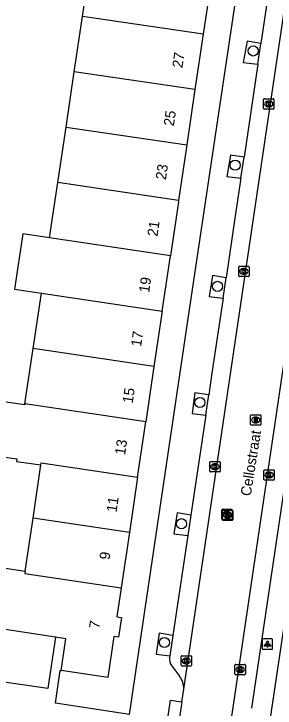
# Model space of a CAD drawing. Extents: x 164150 to 165261, y 382513 to 383432.
# Drawn here: x 164314.2 to 164339.4, y 382927.8 to 382994.8 of the extents above; entities that cross this region are included whole.
import ezdxf

# ---------------------------------------------------------------- set-up
doc = ezdxf.new("R2010")
doc.units = 0
for name, color, linetype in [('IMGEO_Boom', 7, 'Continuous'), ('IMGEO_Kolk', 7, 'Continuous'), ('IMGEO_Lichtpunt', 7, 'Continuous'), ('IMGEO_Openbare_ruimte_label', 7, 'Continuous'), ('IMGEO_Pand', 7, 'Continuous'), ('IMGEO_Pand_nummerreeks', 7, 'Continuous'), ('IMGEO_Parkeervlak_open', 7, 'Continuous'), ('IMGEO_Rijbaan_lokaal_open', 7, 'Continuous'), ('IMGEO_Rioolput', 7, 'Continuous'), ('IMGEO_Voetpad_open', 7, 'Continuous')]:
    doc.layers.add(name, color=color, linetype=linetype)

msp = doc.modelspace()

# ---------------------------------------------------------------- linework, layer by layer
at = {"layer": 'IMGEO_Boom'}
for centre in [(164337.291, 382991.232), (164335.553, 382980.21), (164333.847, 382968.518), (164332.146, 382957.302), (164330.362, 382945.609), (164328.715, 382934.147)]:
    msp.add_circle(centre, 0.489, dxfattribs=at)
at = {"layer": 'IMGEO_Kolk'}
for p, q in [((164338.283, 382985.695), (164338.283, 382986.547)), ((164338.358, 382986.621), (164339.21, 382986.621)), ((164338.771, 382986.401), (164338.796, 382986.401)), ((164339.284, 382986.547), (164339.284, 382985.695)), ((164339.21, 382985.621), (164338.358, 382985.621)), ((164338.794, 382985.841), (164338.769, 382985.841)), ((164335.89, 382969.532), (164335.89, 382970.384)), ((164335.965, 382970.458), (164336.817, 382970.458)), ((164336.378, 382970.238), (164336.403, 382970.238)), ((164336.891, 382970.384), (164336.891, 382969.532)), ((164336.401, 382969.678), (164336.376, 382969.678)), ((164336.817, 382969.458), (164335.965, 382969.458)), ((164333.098, 382950.684), (164333.098, 382951.536)), ((164333.173, 382951.61), (164334.025, 382951.61)), ((164334.099, 382951.536), (164334.099, 382950.684)), ((164333.609, 382950.83), (164333.584, 382950.83)), ((164333.586, 382951.39), (164333.611, 382951.39)), ((164338.312, 382949.883), (164338.312, 382950.735)), ((164338.387, 382950.809), (164339.239, 382950.809)), ((164339.313, 382950.735), (164339.313, 382949.883)), ((164334.025, 382950.61), (164333.173, 382950.61)), ((164338.8, 382950.589), (164338.825, 382950.589)), ((164339.239, 382949.809), (164338.387, 382949.809)), ((164338.823, 382950.029), (164338.798, 382950.029)), ((164330.332, 382931.941), (164330.332, 382932.793)), ((164330.407, 382932.867), (164331.259, 382932.867)), ((164330.82, 382932.647), (164330.845, 382932.647)), ((164331.333, 382932.793), (164331.333, 382931.941)), ((164330.843, 382932.087), (164330.818, 382932.087)), ((164335.6, 382932.034), (164336.452, 382932.034)), ((164331.259, 382931.867), (164330.407, 382931.867)), ((164335.525, 382931.108), (164335.525, 382931.96)), ((164336.013, 382931.814), (164336.038, 382931.814)), ((164336.526, 382931.96), (164336.526, 382931.108)), ((164336.452, 382931.034), (164335.6, 382931.034)), ((164336.036, 382931.254), (164336.011, 382931.254))]:
    msp.add_line(p, q, dxfattribs=at)
for points in [[(164338.283, 382985.695), (164338.283, 382986.547)], [(164338.358, 382986.621), (164339.21, 382986.621)], [(164338.604, 382986.321), (164338.727, 382986.321), (164338.727, 382986.17), (164338.857, 382986.321), (164339.021, 382986.321), (164338.875, 382986.17), (164339.028, 382985.921), (164338.876, 382985.921), (164338.791, 382986.085), (164338.727, 382986.018), (164338.727, 382985.921), (164338.604, 382985.921), (164338.604, 382986.321)], [(164339.284, 382986.547), (164339.284, 382985.695)], [(164339.21, 382985.621), (164338.358, 382985.621)], [(164335.89, 382969.532), (164335.89, 382970.384)], [(164335.965, 382970.458), (164336.817, 382970.458)], [(164336.891, 382970.384), (164336.891, 382969.532)], [(164336.211, 382970.158), (164336.334, 382970.158), (164336.334, 382970.007), (164336.464, 382970.158), (164336.628, 382970.158), (164336.482, 382970.007), (164336.635, 382969.758), (164336.483, 382969.758), (164336.398, 382969.922), (164336.334, 382969.855), (164336.334, 382969.758), (164336.211, 382969.758), (164336.211, 382970.158)], [(164336.817, 382969.458), (164335.965, 382969.458)], [(164333.098, 382950.684), (164333.098, 382951.536)], [(164333.173, 382951.61), (164334.025, 382951.61)], [(164334.099, 382951.536), (164334.099, 382950.684)], [(164333.419, 382951.31), (164333.542, 382951.31), (164333.542, 382951.159), (164333.672, 382951.31), (164333.836, 382951.31), (164333.69, 382951.159), (164333.843, 382950.91), (164333.691, 382950.91), (164333.606, 382951.074), (164333.542, 382951.007), (164333.542, 382950.91), (164333.419, 382950.91), (164333.419, 382951.31)], [(164338.312, 382949.883), (164338.312, 382950.735)], [(164338.387, 382950.809), (164339.239, 382950.809)], [(164339.313, 382950.735), (164339.313, 382949.883)], [(164334.025, 382950.61), (164333.173, 382950.61)], [(164338.633, 382950.509), (164338.756, 382950.509), (164338.756, 382950.358), (164338.886, 382950.509), (164339.05, 382950.509), (164338.904, 382950.358), (164339.057, 382950.109), (164338.905, 382950.109), (164338.82, 382950.273), (164338.756, 382950.206), (164338.756, 382950.109), (164338.633, 382950.109), (164338.633, 382950.509)], [(164339.239, 382949.809), (164338.387, 382949.809)], [(164330.332, 382931.941), (164330.332, 382932.793)], [(164330.407, 382932.867), (164331.259, 382932.867)], [(164331.333, 382932.793), (164331.333, 382931.941)], [(164330.653, 382932.567), (164330.776, 382932.567), (164330.776, 382932.416), (164330.906, 382932.567), (164331.07, 382932.567), (164330.924, 382932.416), (164331.077, 382932.167), (164330.925, 382932.167), (164330.84, 382932.331), (164330.776, 382932.264), (164330.776, 382932.167), (164330.653, 382932.167), (164330.653, 382932.567)], [(164335.6, 382932.034), (164336.452, 382932.034)], [(164331.259, 382931.867), (164330.407, 382931.867)], [(164335.525, 382931.108), (164335.525, 382931.96)], [(164335.846, 382931.734), (164335.969, 382931.734), (164335.969, 382931.583), (164336.099, 382931.734), (164336.263, 382931.734), (164336.117, 382931.583), (164336.27, 382931.334), (164336.118, 382931.334), (164336.033, 382931.498), (164335.969, 382931.431), (164335.969, 382931.334), (164335.846, 382931.334), (164335.846, 382931.734)], [(164336.526, 382931.96), (164336.526, 382931.108)], [(164336.452, 382931.034), (164335.6, 382931.034)]]:
    msp.add_lwpolyline(points, dxfattribs=at)
for centre, start, end in [((164338.36, 382986.545), 91.55205, 178.44795), ((164338.36, 382986.545), 91.55205, 178.44795), ((164339.208, 382986.545), 1.55205, 88.44795), ((164339.208, 382986.545), 1.55205, 88.44795), ((164338.36, 382985.697), 181.55205, 268.44795), ((164338.36, 382985.697), 181.55205, 268.44795), ((164339.208, 382985.697), 271.55205, 358.44795), ((164339.208, 382985.697), 271.55205, 358.44795), ((164335.967, 382970.382), 91.55205, 178.44795), ((164335.967, 382970.382), 91.55205, 178.44795), ((164336.815, 382970.382), 1.55205, 88.44795), ((164336.815, 382970.382), 1.55205, 88.44795), ((164335.967, 382969.534), 181.55205, 268.44795), ((164335.967, 382969.534), 181.55205, 268.44795), ((164336.815, 382969.534), 271.55205, 358.44795), ((164336.815, 382969.534), 271.55205, 358.44795), ((164333.175, 382951.534), 91.55205, 178.44795), ((164333.175, 382951.534), 91.55205, 178.44795), ((164334.023, 382951.534), 1.55205, 88.44795), ((164334.023, 382951.534), 1.55205, 88.44795), ((164338.389, 382950.733), 91.55205, 178.44795), ((164338.389, 382950.733), 91.55205, 178.44795), ((164339.237, 382950.733), 1.55205, 88.44795), ((164339.237, 382950.733), 1.55205, 88.44795), ((164333.175, 382950.686), 181.55205, 268.44795), ((164333.175, 382950.686), 181.55205, 268.44795), ((164334.023, 382950.686), 271.55205, 358.44795), ((164334.023, 382950.686), 271.55205, 358.44795), ((164338.389, 382949.885), 181.55205, 268.44795), ((164338.389, 382949.885), 181.55205, 268.44795), ((164339.237, 382949.885), 271.55205, 358.44795), ((164339.237, 382949.885), 271.55205, 358.44795), ((164330.409, 382932.791), 91.55205, 178.44795), ((164330.409, 382932.791), 91.55205, 178.44795), ((164331.257, 382932.791), 1.55205, 88.44795), ((164331.257, 382932.791), 1.55205, 88.44795), ((164335.602, 382931.958), 91.55205, 178.44795), ((164335.602, 382931.958), 91.55205, 178.44795), ((164336.45, 382931.958), 1.55205, 88.44795), ((164336.45, 382931.958), 1.55205, 88.44795), ((164330.409, 382931.943), 181.55205, 268.44795), ((164330.409, 382931.943), 181.55205, 268.44795), ((164331.257, 382931.943), 271.55205, 358.44795), ((164331.257, 382931.943), 271.55205, 358.44795), ((164335.602, 382931.11), 181.55205, 268.44795), ((164335.602, 382931.11), 181.55205, 268.44795), ((164336.45, 382931.11), 271.55205, 358.44795), ((164336.45, 382931.11), 271.55205, 358.44795)]:
    msp.add_arc(centre, 0.0765, start, end, dxfattribs=at)
for centre, major_axis, ratio, start_param, end_param in [((164338.77, 382986.121), (-0.387, 0.002), 0.722429, 4.712389, 7.853982), ((164338.795, 382986.121), (-0.39, 0.002), 0.717154, 1.570796, 4.712389), ((164336.377, 382969.958), (-0.387, 0.002), 0.722429, 4.712389, 7.853982), ((164336.402, 382969.958), (-0.39, 0.002), 0.717154, 1.570796, 4.712389), ((164333.585, 382951.11), (-0.387, 0.002), 0.722429, 4.712389, 7.853982), ((164333.61, 382951.11), (-0.39, 0.002), 0.717154, 1.570796, 4.712389), ((164338.799, 382950.309), (-0.387, 0.002), 0.722429, 4.712389, 7.853982), ((164338.824, 382950.309), (-0.39, 0.002), 0.717154, 1.570796, 4.712389), ((164330.819, 382932.367), (-0.387, 0.002), 0.722429, 4.712389, 7.853982), ((164330.844, 382932.367), (-0.39, 0.002), 0.717154, 1.570796, 4.712389), ((164336.012, 382931.534), (-0.387, 0.002), 0.722429, 4.712389, 7.853982), ((164336.037, 382931.534), (-0.39, 0.002), 0.717154, 1.570796, 4.712389)]:
    msp.add_ellipse(centre, major_axis=major_axis, ratio=ratio, start_param=start_param, end_param=end_param, dxfattribs=at)
at = {"layer": 'IMGEO_Lichtpunt'}
for p, q in [((164338.163, 382934.391), (164338.163, 382933.584)), ((164338.163, 382934.391), (164338.163, 382933.584)), ((164339.065, 382934.486), (164338.257, 382934.486)), ((164339.065, 382934.486), (164338.257, 382934.486)), ((164339.159, 382933.584), (164339.159, 382934.391)), ((164339.159, 382933.584), (164339.159, 382934.391)), ((164338.257, 382933.49), (164339.065, 382933.49)), ((164338.257, 382933.49), (164339.065, 382933.49))]:
    msp.add_line(p, q, dxfattribs=at)
for points in [[(164338.537, 382934.055), (164338.576, 382934.027), (164338.388, 382933.765), (164338.35, 382933.792), (164338.537, 382934.055)], [(164338.639, 382934.007), (164338.686, 382934.007), (164338.686, 382933.685), (164338.639, 382933.685), (164338.639, 382934.007)], [(164338.749, 382934.027), (164338.787, 382934.054), (164338.974, 382933.792), (164338.935, 382933.764), (164338.749, 382934.027)]]:
    msp.add_lwpolyline(points, dxfattribs=at)
msp.add_circle((164338.662, 382934.189), 0.0994, dxfattribs=at)
for centre, start, end in [((164338.257, 382934.391), 90, 180), ((164338.257, 382934.391), 90, 180), ((164339.065, 382934.391), 0, 90), ((164339.065, 382934.391), 0, 90), ((164338.257, 382933.584), 180, 270), ((164338.257, 382933.584), 180, 270), ((164339.065, 382933.584), 270, 0), ((164339.065, 382933.584), 270, 360)]:
    msp.add_arc(centre, 0.0946, start, end, dxfattribs=at)
at = {"layer": 'IMGEO_Pand'}
for points in [[(164320.82, 382994.569), (164321.613, 382999.909)], [(164333.248, 382998.185), (164332.457, 382992.844)], [(164320.027, 382989.227), (164320.82, 382994.569)], [(164332.457, 382992.844), (164320.82, 382994.569)], [(164332.457, 382992.844), (164331.667, 382987.502)], [(164319.233, 382983.885), (164320.027, 382989.227)], [(164331.667, 382987.502), (164320.027, 382989.227)], [(164331.667, 382987.502), (164330.877, 382982.159)], [(164318.44, 382978.544), (164319.233, 382983.885)], [(164319.233, 382983.885), (164330.877, 382982.159)], [(164330.877, 382982.159), (164330.086, 382976.818)], [(164317.647, 382973.203), (164318.44, 382978.544)], [(164330.086, 382976.818), (164318.44, 382978.544)], [(164330.086, 382976.818), (164330.067, 382976.687), (164329.295, 382971.476)], [(164317.647, 382973.203), (164315.055, 382973.587), (164314.262, 382968.245), (164316.854, 382967.861)], [(164329.295, 382971.476), (164317.647, 382973.203)], [(164328.504, 382966.134), (164329.295, 382971.476)], [(164316.061, 382962.52), (164316.854, 382967.861)], [(164316.854, 382967.861), (164328.504, 382966.134)], [(164328.504, 382966.134), (164327.713, 382960.793)], [(164315.267, 382957.178), (164316.061, 382962.52)], [(164327.713, 382960.793), (164316.061, 382962.52)], [(164327.713, 382960.793), (164326.921, 382955.451)], [(164315.267, 382957.178), (164315.252, 382957.076), (164312.296, 382957.516), (164311.521, 382952.297), (164314.477, 382951.858), (164314.474, 382951.837), (164314.443, 382951.628), (164316.818, 382951.278)], [(164326.921, 382955.451), (164315.267, 382957.178)], [(164326.13, 382950.109), (164326.921, 382955.451)], [(164316.818, 382951.278), (164316.849, 382951.485), (164326.13, 382950.109)], [(164316.061, 382946.143), (164316.818, 382951.278)], [(164326.13, 382950.109), (164325.339, 382944.768)], [(164315.309, 382941.042), (164316.061, 382946.143)], [(164325.339, 382944.768), (164316.061, 382946.143)], [(164325.339, 382944.768), (164324.547, 382939.426)], [(164312.077, 382935.58), (164312.899, 382941.152), (164312.934, 382941.392), (164315.309, 382941.042)], [(164315.309, 382941.042), (164315.273, 382940.8), (164324.547, 382939.426)], [(164324.547, 382939.426), (164324.133, 382936.628), (164324.572, 382936.56), (164324.293, 382934.661), (164323.844, 382934.724), (164323.258, 382930.771), (164318.755, 382931.441)], [(164318.21, 382934.662), (164312.077, 382935.58)], [(164318.755, 382931.441), (164319.207, 382934.513), (164318.21, 382934.662)]]:
    msp.add_lwpolyline(points, dxfattribs=at)
at = {"layer": 'IMGEO_Parkeervlak_open'}
for points in [[(164337.732, 382989.961), (164338.026, 382991.946)], [(164336.099, 382978.955), (164336.401, 382980.987)], [(164334.382, 382967.382), (164334.674, 382969.349)], [(164332.703, 382956.085), (164332.994, 382958.039)], [(164331.264, 382946.433), (164330.972, 382944.473)], [(164329.534, 382934.825), (164329.242, 382932.867)]]:
    msp.add_lwpolyline(points, dxfattribs=at)
at = {"layer": 'IMGEO_Rijbaan_lokaal_open'}
for points in [[(164330.581, 382929.652), (164337.289, 382974.851), (164342.663, 383011.12)], [(164334.976, 382925.26), (164341.922, 382972.289)], [(164318.21, 382934.662), (164317.472, 382929.7), (164305.414, 382931.455), (164306.127, 382936.338)], [(164325.346, 382927.185), (164318.229, 382928.302), (164318.672, 382931.453), (164318.755, 382931.441)], [(164330.414, 382928.426), (164330.581, 382929.652)], [(164330.414, 382928.426), (164329.243, 382920.501)]]:
    msp.add_lwpolyline(points, dxfattribs=at)
at = {"layer": 'IMGEO_Rioolput'}
for p, q in [((164337.101, 382956.114), (164337.953, 382956.114)), ((164337.026, 382955.188), (164337.026, 382956.04)), ((164337.514, 382955.894), (164337.539, 382955.894)), ((164338.027, 382956.04), (164338.027, 382955.188)), ((164337.953, 382955.114), (164337.101, 382955.114)), ((164337.537, 382955.334), (164337.512, 382955.334)), ((164334.25, 382946.079), (164334.25, 382946.931)), ((164334.321, 382946.006), (164334.321, 382946.858)), ((164334.325, 382947.005), (164335.177, 382947.005)), ((164334.396, 382946.932), (164335.248, 382946.932)), ((164334.738, 382946.785), (164334.763, 382946.785)), ((164335.251, 382946.931), (164335.251, 382946.079)), ((164335.322, 382946.858), (164335.322, 382946.006)), ((164334.761, 382946.225), (164334.736, 382946.225)), ((164334.832, 382946.152), (164334.807, 382946.152)), ((164334.809, 382946.712), (164334.834, 382946.712)), ((164335.177, 382946.005), (164334.325, 382946.005)), ((164335.248, 382945.932), (164334.396, 382945.932))]:
    msp.add_line(p, q, dxfattribs=at)
for points in [[(164337.101, 382956.114), (164337.953, 382956.114)], [(164337.026, 382955.188), (164337.026, 382956.04)], [(164337.615, 382955.812), (164337.363, 382955.814), (164337.363, 382955.414)], [(164337.363, 382955.414), (164337.487, 382955.414), (164337.487, 382955.576), (164337.498, 382955.576)], [(164337.541, 382955.733), (164337.487, 382955.733), (164337.487, 382955.652)], [(164337.487, 382955.652), (164337.539, 382955.652)], [(164337.545, 382955.547), (164337.616, 382955.414), (164337.756, 382955.414), (164337.691, 382955.54)], [(164338.027, 382956.04), (164338.027, 382955.188)], [(164337.953, 382955.114), (164337.101, 382955.114)], [(164334.25, 382946.079), (164334.25, 382946.931)], [(164334.321, 382946.006), (164334.321, 382946.858)], [(164334.325, 382947.005), (164335.177, 382947.005)], [(164334.396, 382946.932), (164335.248, 382946.932)], [(164335.251, 382946.931), (164335.251, 382946.079)], [(164335.322, 382946.858), (164335.322, 382946.006)], [(164334.839, 382946.703), (164334.587, 382946.705), (164334.587, 382946.305)], [(164334.587, 382946.305), (164334.711, 382946.305), (164334.711, 382946.467), (164334.722, 382946.467)], [(164334.91, 382946.63), (164334.658, 382946.632), (164334.658, 382946.232)], [(164334.658, 382946.232), (164334.782, 382946.232), (164334.782, 382946.394), (164334.793, 382946.394)], [(164334.765, 382946.624), (164334.711, 382946.624), (164334.711, 382946.543)], [(164334.711, 382946.543), (164334.763, 382946.543)], [(164334.769, 382946.438), (164334.84, 382946.305), (164334.98, 382946.305), (164334.915, 382946.431)], [(164334.836, 382946.551), (164334.782, 382946.551), (164334.782, 382946.47)], [(164334.782, 382946.47), (164334.834, 382946.47)], [(164334.84, 382946.365), (164334.911, 382946.232), (164335.051, 382946.232), (164334.986, 382946.358)], [(164335.177, 382946.005), (164334.325, 382946.005)], [(164335.248, 382945.932), (164334.396, 382945.932)]]:
    msp.add_lwpolyline(points, dxfattribs=at)
for centre, radius, start, end in [((164337.103, 382956.038), 0.0765, 91.55205, 178.44795), ((164337.103, 382956.038), 0.0765, 91.55205, 178.44795), ((164337.951, 382956.038), 0.0765, 1.55205, 88.44795), ((164337.951, 382956.038), 0.0765, 1.55205, 88.44795), ((164337.497, 382955.523), 0.0533, 26.02933, 88.69889), ((164337.523, 382955.841), 0.19, 274.7715, 282.96867), ((164337.547, 382955.637), 0.0964, 77.00612, 93.18647), ((164337.561, 382955.694), 0.0378, 276.66336, 79.67722), ((164337.614, 382955.702), 0.109, 350.36119, 89.41601), ((164337.612, 382955.702), 0.112, 277.58423, 350.98172), ((164337.596, 382955.487), 0.108, 29.51342, 73.79051), ((164337.103, 382955.19), 0.0765, 181.55205, 268.44795), ((164337.103, 382955.19), 0.0765, 181.55205, 268.44795), ((164337.951, 382955.19), 0.0765, 271.55205, 358.44795), ((164337.951, 382955.19), 0.0765, 271.55205, 358.44795), ((164334.327, 382946.929), 0.0765, 91.55205, 178.44795), ((164334.327, 382946.929), 0.0765, 91.55205, 178.44795), ((164334.398, 382946.856), 0.0765, 91.55205, 178.44795), ((164334.398, 382946.856), 0.0765, 91.55205, 178.44795), ((164335.175, 382946.929), 0.0765, 1.55205, 88.44795), ((164335.175, 382946.929), 0.0765, 1.55205, 88.44795), ((164335.246, 382946.856), 0.0765, 1.55205, 88.44795), ((164335.246, 382946.856), 0.0765, 1.55205, 88.44795), ((164334.327, 382946.081), 0.0765, 181.55205, 268.44795), ((164334.327, 382946.081), 0.0765, 181.55205, 268.44795), ((164334.721, 382946.414), 0.0533, 26.02933, 88.69889), ((164334.747, 382946.732), 0.19, 274.7715, 282.96867), ((164334.771, 382946.528), 0.0964, 77.00612, 93.18647), ((164334.785, 382946.585), 0.0378, 276.66336, 79.67722), ((164334.792, 382946.341), 0.0533, 26.02933, 88.69889), ((164334.818, 382946.659), 0.19, 274.7715, 282.96867), ((164334.842, 382946.455), 0.0964, 77.00612, 93.18647), ((164334.838, 382946.593), 0.109, 350.36119, 89.41601), ((164334.836, 382946.593), 0.112, 277.58423, 350.98172), ((164334.82, 382946.378), 0.108, 29.51342, 73.79051), ((164334.856, 382946.512), 0.0378, 276.66336, 79.67722), ((164334.909, 382946.52), 0.109, 350.36119, 89.41601), ((164334.907, 382946.52), 0.112, 277.58423, 350.98172), ((164334.891, 382946.305), 0.108, 29.51342, 73.79051), ((164335.175, 382946.081), 0.0765, 271.55205, 358.44795), ((164335.175, 382946.081), 0.0765, 271.55205, 358.44795), ((164334.398, 382946.008), 0.0765, 181.55205, 268.44795), ((164334.398, 382946.008), 0.0765, 181.55205, 268.44795), ((164335.246, 382946.008), 0.0765, 271.55205, 358.44795), ((164335.246, 382946.008), 0.0765, 271.55205, 358.44795)]:
    msp.add_arc(centre, radius, start, end, dxfattribs=at)
for centre, major_axis, ratio, start_param, end_param in [((164337.513, 382955.614), (-0.387, 0.002), 0.722429, 4.712389, 7.853982), ((164337.538, 382955.614), (-0.39, 0.002), 0.717154, 1.570796, 4.712389), ((164334.737, 382946.505), (-0.387, 0.002), 0.722429, 4.712389, 7.853982), ((164334.762, 382946.505), (-0.39, 0.002), 0.717154, 1.570796, 4.712389), ((164334.808, 382946.432), (-0.387, 0.002), 0.722429, 4.712389, 7.853982), ((164334.833, 382946.432), (-0.39, 0.002), 0.717154, 1.570796, 4.712389)]:
    msp.add_ellipse(centre, major_axis=major_axis, ratio=ratio, start_param=start_param, end_param=end_param, dxfattribs=at)
at = {"layer": 'IMGEO_Voetpad_open'}
for points in [[(164325.346, 382927.185), (164331.117, 382966.047), (164338.115, 383013.045), (164338.399, 383014.963)], [(164339.408, 383001.26), (164338.026, 382991.946)], [(164338.026, 382991.946), (164336.714, 382992.172), (164336.33, 382990.136), (164337.732, 382989.961)], [(164337.732, 382989.961), (164336.401, 382980.987)], [(164336.401, 382980.987), (164335.08, 382981.175), (164334.753, 382979.123), (164336.099, 382978.955)], [(164336.099, 382978.955), (164335.527, 382975.099), (164334.674, 382969.349)], [(164334.647, 382897.854), (164343.748, 382959.071), (164346.307, 382976.27)], [(164334.674, 382969.349), (164333.352, 382969.557), (164333.044, 382967.547), (164334.382, 382967.382)], [(164343.279, 382969.354), (164341.819, 382959.471), (164337.13, 382927.812)], [(164334.382, 382967.382), (164333.34, 382960.358), (164332.994, 382958.039)], [(164332.994, 382958.039), (164331.67, 382958.244), (164331.386, 382956.233), (164332.703, 382956.085)], [(164332.703, 382956.085), (164331.264, 382946.433)], [(164331.264, 382946.433), (164329.946, 382946.65), (164329.638, 382944.637), (164330.972, 382944.473)], [(164330.972, 382944.473), (164329.534, 382934.825)], [(164329.534, 382934.825), (164328.204, 382935.035), (164327.93, 382933.022), (164329.242, 382932.867)], [(164329.242, 382932.867), (164329.213, 382932.674)], [(164329.414, 382931.92), (164330.167, 382930.911)], [(164329.243, 382920.501), (164328.139, 382920.691), (164329.307, 382928.575), (164330.414, 382928.426)]]:
    msp.add_lwpolyline(points, dxfattribs=at)
for centre, radius, start, end in [((164330.357, 382932.575), 1.148, 175.06026, 214.79311), ((164328.641, 382929.712), 1.941, 358.23768, 38.1674)]:
    msp.add_arc(centre, radius, start, end, dxfattribs=at)

# ---------------------------------------------------------------- texts
at = {"layer": 'IMGEO_Openbare_ruimte_label'}
msp.add_text('Cellostraat', height=1, rotation=80.91425, dxfattribs=at).set_placement((164337.041, 382948.223))
at = {"layer": 'IMGEO_Pand_nummerreeks'}
for s, rotation, p in [('27', 81.58346, (164330.455, 382989.554)), ('25', 81.58346, (164329.624, 382983.939)), ('23', 81.58346, (164328.857, 382978.758)), ('21', 81.572, (164328.047, 382973.29)), ('19', 81.572, (164327.242, 382967.857)), ('17', 81.572, (164326.47, 382962.647)), ('15', 81.572, (164325.66, 382957.178)), ('13', 81.572, (164324.921, 382952.187)), ('11', 81.572, (164324.103, 382946.667)), ('9', 81.572, (164323.425, 382942.084)), ('7', 81.56627, (164322.435, 382935.448))]:
    msp.add_text(s, height=1, rotation=rotation, dxfattribs=at).set_placement(p)

doc.saveas('drawing.dxf')
